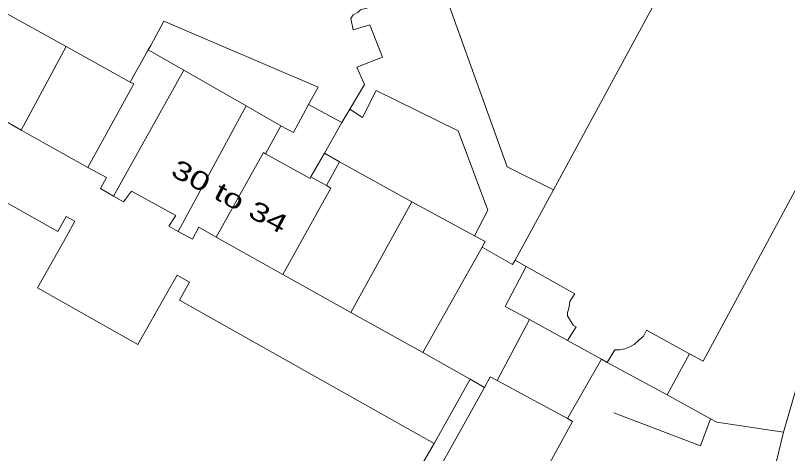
# Model space of a CAD drawing. Extents: x 528790 to 529292, y 179350 to 179856.
# Drawn here: x 528898.3 to 528960.3, y 179400 to 179435.2 of the extents above; entities that cross this region are included whole.
import ezdxf

# ---------------------------------------------------------------- set-up
doc = ezdxf.new("R2010")
doc.units = 0
doc.header["$LTSCALE"] = 0.6
doc.layers.add('1', color=7, linetype='Continuous', lineweight=13)
doc.layers.add('2', color=7, linetype='Continuous', lineweight=13)
doc.layers.add('5', color=7, linetype='Continuous')

msp = doc.modelspace()

# ---------------------------------------------------------------- linework, layer by layer
at = {"layer": '1'}
for points in [[(528971.05, 179473.6), (528970.6, 179479), (528961.15, 179477.2), (528957.8, 179457.55), (528956.2, 179454.6), (528951.98, 179456.87), (528951.49, 179455.7), (528943.42, 179446.38), (528938.74, 179442.76), (528935.52, 179441.13), (528932.41, 179439.47), (528932.4, 179437.9), (528937.76, 179423), (528941.48, 179421.16), (528949.6, 179436.1), (528949.55, 179436.55), (528956.8, 179450), (528957.35, 179450.05), (528968.6, 179471.1), (528969.6, 179470.75)], [(528925.13, 179427.62), (528926.15, 179426.97), (528927.24, 179429.12), (528933.83, 179425.88), (528936.2, 179419.51), (528935.13, 179417.47), (528936, 179417), (528935.75, 179416.55), (528938.2, 179415.15), (528938.4, 179415.5), (528941.48, 179421.16), (528937.76, 179423), (528932.4, 179437.9), (528931, 179437.4), (528927.45, 179436), (528926, 179435.6), (528925.8, 179435.4), (528925.4, 179435.2), (528925.2, 179434.9), (528925.4, 179434), (528926.75, 179434.4), (528927.75, 179431.8), (528925.7, 179431), (528926.3, 179429.6)], [(528902.35, 179432.65), (528897, 179435.6), (528893.35, 179429), (528898.75, 179425.95)], [(528919.6, 179426.3), (528920.6, 179425.75), (528921.8, 179428), (528922.6, 179429.4), (528910.2, 179434.7), (528909.15, 179432.75), (528908.95, 179432.4), (528911.8, 179430.75), (528916.8, 179427.9)], [(528959.95, 179401.7), (528962.3, 179409.8), (528965, 179417.8), (528968.8, 179427.9), (528970.4, 179432.2), (528968, 179433.45), (528965.2, 179428.3), (528964.75, 179428.25), (528953.5, 179407.4), (528952.4, 179408), (528950.6, 179404.7), (528954.091, 179402.78), (528954.6, 179402.5)], [(528898.75, 179425.95), (528904.1, 179422.95), (528907.8, 179429.65), (528907.5, 179429.8), (528902.35, 179432.65)], [(528911.8, 179430.75), (528908.95, 179432.4), (528907.5, 179429.8), (528907.8, 179429.65), (528904.1, 179422.95), (528905.6, 179422.15), (528905.1, 179421.25), (528906.15, 179420.65)], [(528916.8, 179427.9), (528911.8, 179430.75), (528906.15, 179420.65), (528906.95, 179420.2), (528907.6, 179421.05), (528911.15, 179419.1), (528910.6, 179418.25), (528911.35, 179417.8)], [(528924.3, 179423.4), (528930.1, 179420.2), (528935.13, 179417.47), (528936.2, 179419.51), (528933.83, 179425.88), (528927.24, 179429.12), (528926.15, 179426.97), (528925.13, 179427.62), (528924.5, 179426.55), (528923.1, 179424.1)], [(528919.6, 179426.3), (528916.8, 179427.9), (528911.35, 179417.8), (528912.5, 179417.2), (528913, 179418.15), (528914.4, 179417.35), (528918.2, 179424.15), (528918.35, 179424.05)], [(528918.35, 179424.05), (528921.95, 179422.05), (528922, 179422.2), (528923.1, 179424.1), (528924.5, 179426.55), (528921.8, 179428), (528920.6, 179425.75), (528919.6, 179426.3)], [(528923.25, 179421.5), (528922, 179422.2), (528921.95, 179422.05), (528918.35, 179424.05), (528918.2, 179424.15), (528914.4, 179417.35), (528919.75, 179414.35), (528923.6, 179421.3)], [(528923.25, 179421.5), (528924.3, 179423.4), (528923.1, 179424.1), (528922, 179422.2)], [(528925.2, 179411.3), (528930.1, 179420.2), (528924.3, 179423.4), (528923.25, 179421.5), (528923.6, 179421.3), (528919.75, 179414.35)], [(528935.75, 179416.55), (528936, 179417), (528935.13, 179417.47), (528930.1, 179420.2), (528925.2, 179411.3), (528931, 179408.1)], [(528936.95, 179405.85), (528939.55, 179410.75), (528937.6, 179411.8), (528939.3, 179415), (528938.4, 179415.5), (528938.2, 179415.15), (528935.75, 179416.55), (528931, 179408.1), (528934.8, 179405.95), (528935.95, 179405.3), (528936.4, 179406.15)], [(528942.6, 179409.05), (528943.3, 179410.15), (528943.05, 179410.3), (528942.6, 179411.05), (528942.6, 179411.3), (528942.7, 179411.55), (528942.75, 179411.8), (528942.8, 179412.2), (528943, 179412.55), (528943.2, 179412.8), (528939.3, 179415), (528937.6, 179411.8), (528939.55, 179410.75)], [(528936.95, 179405.85), (528942.6, 179402.8), (528945.35, 179407.55), (528942.6, 179409.05), (528939.55, 179410.75)], [(528952.4, 179408), (528948.95, 179409.9), (528948.7, 179409.4), (528948.3, 179409.05), (528947.95, 179408.75), (528947.6, 179408.55), (528947.2, 179408.4), (528946.8, 179408.3), (528946.4, 179408.3), (528945.8, 179407.3), (528950.6, 179404.7)], [(528938.3, 179393.9), (528938.6, 179394.5), (528943, 179402.55), (528942.6, 179402.8), (528936.95, 179405.85), (528936.4, 179406.15), (528935.95, 179405.3), (528922.6, 179381.4), (528921.8, 179381.9), (528920.8, 179380), (528921, 179379.85), (528921.5, 179379.6), (528921.8, 179379.8), (528928.4, 179376.1), (528929.05, 179375.6), (528930.05, 179377.4), (528929.4, 179377.8)], [(528921.8, 179381.9), (528922.6, 179381.4), (528935.95, 179405.3), (528934.8, 179405.95), (528931.9, 179400.8), (528930.6, 179398.55), (528930, 179398.9), (528920.8, 179382.5)]]:
    msp.add_lwpolyline(points, close=True, dxfattribs=at)
for points in [[(528949.6, 179436.1), (528941.48, 179421.16), (528938.4, 179415.5), (528939.3, 179415), (528943.2, 179412.8), (528943, 179412.55), (528942.8, 179412.2), (528942.75, 179411.8), (528942.7, 179411.55), (528942.6, 179411.3), (528942.6, 179411.05), (528943.05, 179410.3), (528943.3, 179410.15), (528942.6, 179409.05), (528945.35, 179407.55), (528945.8, 179407.3), (528946.4, 179408.3), (528946.8, 179408.3), (528947.2, 179408.4), (528947.6, 179408.55), (528947.95, 179408.75), (528948.3, 179409.05), (528948.7, 179409.4), (528948.95, 179409.9), (528952.4, 179408), (528953.5, 179407.4), (528964.75, 179428.25)], [(528897, 179435.6), (528902.35, 179432.65), (528907.5, 179429.8), (528908.95, 179432.4), (528909.15, 179432.75), (528910.2, 179434.7), (528922.6, 179429.4), (528921.8, 179428), (528924.5, 179426.55), (528925.13, 179427.62), (528926.3, 179429.6), (528925.7, 179431), (528927.75, 179431.8), (528926.75, 179434.4), (528925.4, 179434), (528925.2, 179434.9), (528925.4, 179435.2)], [(528881.8, 179429), (528901.688, 179417.809), (528902.369, 179419.02), (528903.061, 179418.631), (528902.38, 179417.42), (528900.05, 179413.29), (528908.12, 179408.74), (528910.45, 179412.87), (528911.257, 179414.303), (528912.253, 179413.743), (528911.446, 179412.309), (528931.9, 179400.8), (528934.8, 179405.95), (528931, 179408.1), (528925.2, 179411.3), (528919.75, 179414.35), (528914.4, 179417.35), (528913, 179418.15), (528912.5, 179417.2), (528911.35, 179417.8), (528910.6, 179418.25), (528911.15, 179419.1), (528907.6, 179421.05), (528906.95, 179420.2), (528906.15, 179420.65), (528905.1, 179421.25), (528905.6, 179422.15), (528904.1, 179422.95), (528898.75, 179425.95), (528893.35, 179429)], [(528897.956, 179356.024), (528905.826, 179356.024), (528916.8, 179375.25), (528917.8, 179374.65), (528918.9, 179376.55), (528921, 179379.85), (528920.8, 179380), (528921.8, 179381.9), (528920.8, 179382.5), (528930, 179398.9), (528930.6, 179398.55), (528931.9, 179400.8), (528911.446, 179412.309), (528912.253, 179413.743), (528911.257, 179414.303), (528910.45, 179412.87), (528908.12, 179408.74), (528900.05, 179413.29), (528902.38, 179417.42), (528903.061, 179418.631), (528902.369, 179419.02), (528901.688, 179417.809), (528881.8, 179429)], [(528962.3, 179409.8), (528959.95, 179401.7), (528957.4, 179391.2)], [(528957.4, 179391.2), (528959.95, 179401.7), (528954.6, 179402.5), (528954.091, 179402.78), (528950.6, 179404.7), (528945.8, 179407.3), (528945.35, 179407.55), (528942.6, 179402.8), (528943, 179402.55), (528938.6, 179394.5)]]:
    msp.add_lwpolyline(points, dxfattribs=at)
at = {"layer": '2'}
for p, q in [((528897, 179435.6), (528902.35, 179432.65)), ((528898.75, 179425.95), (528902.35, 179432.65)), ((528902.35, 179432.65), (528907.5, 179429.8)), ((528907.5, 179429.8), (528908.95, 179432.4)), ((528908.95, 179432.4), (528911.8, 179430.75)), ((528906.15, 179420.65), (528911.8, 179430.75)), ((528911.8, 179430.75), (528916.8, 179427.9)), ((528893.35, 179429), (528898.75, 179425.95)), ((528911.35, 179417.8), (528916.8, 179427.9)), ((528916.8, 179427.9), (528919.6, 179426.3)), ((528921.8, 179428), (528924.5, 179426.55)), ((528925.13, 179427.62), (528924.5, 179426.55)), ((528924.5, 179426.55), (528923.1, 179424.1)), ((528898.75, 179425.95), (528904.1, 179422.95)), ((528919.6, 179426.3), (528918.35, 179424.05)), ((528923.1, 179424.1), (528922, 179422.2)), ((528923.1, 179424.1), (528924.3, 179423.4)), ((528924.3, 179423.4), (528923.25, 179421.5)), ((528924.3, 179423.4), (528930.1, 179420.2)), ((528922, 179422.2), (528923.25, 179421.5)), ((528938.4, 179415.5), (528941.48, 179421.16)), ((528930.1, 179420.2), (528925.2, 179411.3)), ((528930.1, 179420.2), (528935.13, 179417.47)), ((528914.4, 179417.35), (528919.75, 179414.35)), ((528931, 179408.1), (528935.75, 179416.55)), ((528938.4, 179415.5), (528939.3, 179415)), ((528919.75, 179414.35), (528925.2, 179411.3)), ((528925.2, 179411.3), (528931, 179408.1)), ((528939.55, 179410.75), (528936.95, 179405.85)), ((528942.6, 179409.05), (528939.55, 179410.75)), ((528945.35, 179407.55), (528942.6, 179409.05)), ((528931, 179408.1), (528934.8, 179405.95)), ((528950.6, 179404.7), (528952.4, 179408)), ((528945.35, 179407.55), (528942.6, 179402.8)), ((528945.8, 179407.3), (528945.35, 179407.55)), ((528950.6, 179404.7), (528945.8, 179407.3)), ((528931.9, 179400.8), (528934.8, 179405.95)), ((528934.8, 179405.95), (528935.95, 179405.3)), ((528936.95, 179405.85), (528942.6, 179402.8)), ((528954.091, 179402.78), (528950.6, 179404.7))]:
    msp.add_line(p, q, dxfattribs=at)
for points in [[(528941.48, 179421.16), (528949.6, 179436.1), (528949.55, 179436.55), (528956.8, 179450), (528957.35, 179450.05), (528968.6, 179471.1), (528969.6, 179470.75), (528971.05, 179473.6)], [(528941.48, 179421.16), (528937.76, 179423), (528932.4, 179437.9)], [(528926, 179435.6), (528925.8, 179435.4), (528925.4, 179435.2), (528925.2, 179434.9), (528925.4, 179434), (528926.75, 179434.4), (528927.75, 179431.8), (528925.7, 179431), (528926.3, 179429.6), (528925.13, 179427.62)], [(528908.95, 179432.4), (528909.15, 179432.75), (528910.2, 179434.7), (528922.6, 179429.4), (528921.8, 179428)], [(528952.4, 179408), (528953.5, 179407.4), (528964.75, 179428.25), (528965.2, 179428.3), (528968, 179433.45)], [(528970.4, 179432.2), (528968.8, 179427.9), (528965, 179417.8), (528962.3, 179409.8), (528959.95, 179401.7)], [(528907.5, 179429.8), (528907.8, 179429.65), (528904.1, 179422.95)], [(528881.8, 179429), (528901.688, 179417.809), (528902.369, 179419.02), (528903.061, 179418.631), (528902.38, 179417.42), (528900.05, 179413.29), (528908.12, 179408.74), (528910.45, 179412.87), (528911.257, 179414.303), (528912.253, 179413.743), (528911.446, 179412.309), (528931.9, 179400.8)], [(528935.13, 179417.47), (528936.2, 179419.51), (528933.83, 179425.88), (528927.24, 179429.12), (528926.15, 179426.97), (528925.13, 179427.62)], [(528919.6, 179426.3), (528920.6, 179425.75), (528921.8, 179428)], [(528918.35, 179424.05), (528918.2, 179424.15), (528914.4, 179417.35)], [(528922, 179422.2), (528921.95, 179422.05), (528918.35, 179424.05)], [(528904.1, 179422.95), (528905.6, 179422.15), (528905.1, 179421.25), (528906.15, 179420.65)], [(528906.15, 179420.65), (528906.95, 179420.2), (528907.6, 179421.05), (528911.15, 179419.1), (528910.6, 179418.25), (528911.35, 179417.8)], [(528923.25, 179421.5), (528923.6, 179421.3), (528919.75, 179414.35)], [(528911.35, 179417.8), (528912.5, 179417.2), (528913, 179418.15), (528914.4, 179417.35)], [(528935.13, 179417.47), (528936, 179417), (528935.75, 179416.55)], [(528935.75, 179416.55), (528938.2, 179415.15), (528938.4, 179415.5)], [(528939.55, 179410.75), (528937.6, 179411.8), (528939.3, 179415)], [(528939.3, 179415), (528943.2, 179412.8), (528943, 179412.55), (528942.8, 179412.2), (528942.75, 179411.8), (528942.7, 179411.55), (528942.6, 179411.3), (528942.6, 179411.05), (528943.05, 179410.3), (528943.3, 179410.15), (528942.6, 179409.05)], [(528945.8, 179407.3), (528946.4, 179408.3), (528946.8, 179408.3), (528947.2, 179408.4), (528947.6, 179408.55), (528947.95, 179408.75), (528948.3, 179409.05), (528948.7, 179409.4), (528948.95, 179409.9), (528952.4, 179408)], [(528935.95, 179405.3), (528936.4, 179406.15), (528936.95, 179405.85)], [(528921.8, 179381.9), (528922.6, 179381.4), (528935.95, 179405.3)], [(528954.091, 179402.78), (528953.298, 179400.615), (528946.339, 179403.265)], [(528942.6, 179402.8), (528943, 179402.55), (528938.6, 179394.5)], [(528959.95, 179401.7), (528954.6, 179402.5), (528954.091, 179402.78)], [(528959.95, 179401.7), (528957.4, 179391.2), (528957.4, 179390.8)], [(528921.8, 179381.9), (528920.8, 179382.5), (528930, 179398.9), (528930.6, 179398.55), (528931.9, 179400.8)]]:
    msp.add_lwpolyline(points, dxfattribs=at)

# ---------------------------------------------------------------- texts
at = {"layer": '5', "width": 1.4}
msp.add_text('30 to 34', height=1.5, rotation=332, dxfattribs=at).set_placement((528910.65, 179422.35))

doc.saveas('drawing.dxf')
